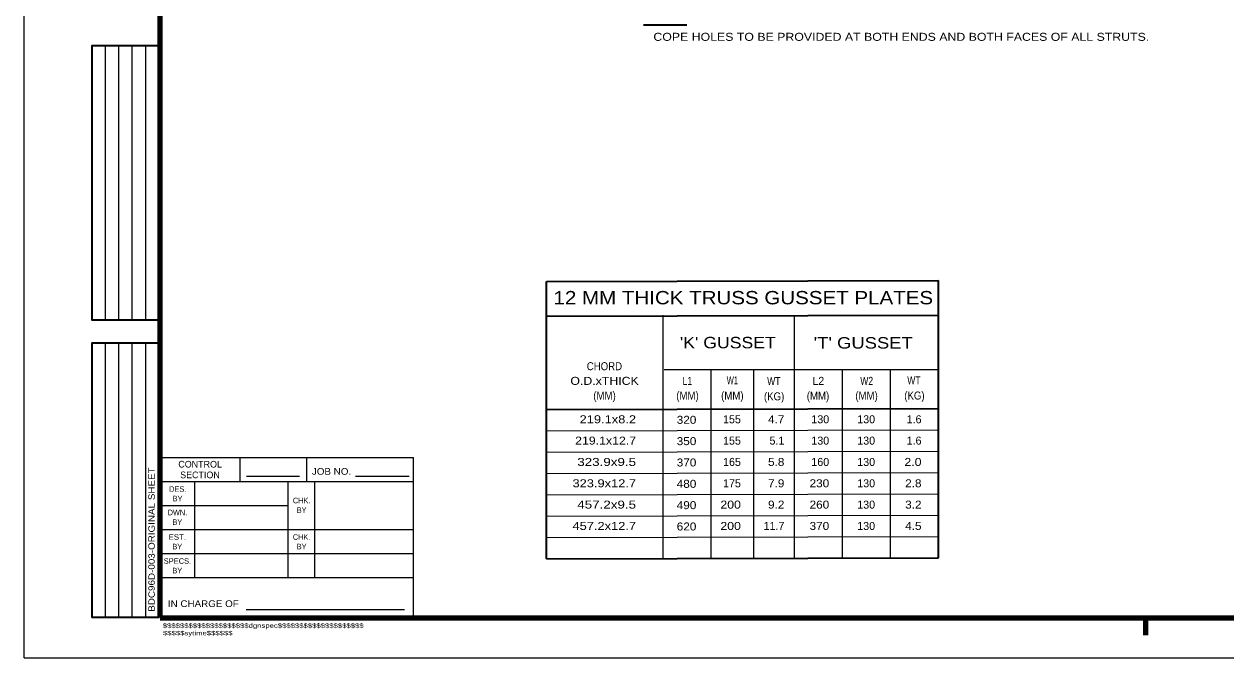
# Model space of a CAD drawing. Extents: x 312601.858 to 312602.699, y 144420.109 to 144420.704.
# Drawn here: x 312601.8578 to 312602.3083, y 144420.1095 to 144420.3472 of the extents above; entities that cross this region are included whole.
import ezdxf
from ezdxf.enums import TextEntityAlignment as Align

# ---------------------------------------------------------------- set-up
doc = ezdxf.new("R2010")
doc.units = 0
doc.header["$LTSCALE"] = 0.0012
for name, color, linetype, lineweight in [('1', 7, 'Continuous', 13), ('2', 7, 'Continuous', 13), ('39', 7, 'Continuous', 13), ('60', 7, 'Continuous', 25)]:
    doc.layers.add(name, color=color, linetype=linetype, lineweight=lineweight)

msp = doc.modelspace()

# ---------------------------------------------------------------- linework, layer by layer
at = {"layer": '1', "lineweight": 35}
for p, q in [((312602.0536, 144420.2507), (312602.2006, 144420.251)), ((312602.0536, 144420.1467), (312602.0536, 144420.2507)), ((312602.2006, 144420.147), (312602.2006, 144420.251)), ((312602.0536, 144420.2377), (312602.2006, 144420.238)), ((312602.0536, 144420.2027), (312602.2006, 144420.203)), ((312602.0536, 144420.1467), (312602.2006, 144420.147))]:
    msp.add_line(p, q, dxfattribs=at)
at = {"layer": '1', "lineweight": 25}
for p, q in [((312602.0974, 144420.147), (312602.0974, 144420.238)), ((312602.1466, 144420.147), (312602.1466, 144420.238)), ((312602.0977, 144420.2177), (312602.2006, 144420.2177))]:
    msp.add_line(p, q, dxfattribs=at)
at = {"layer": '1'}
for p, q in [((312602.1154, 144420.147), (312602.1154, 144420.2177)), ((312602.1314, 144420.147), (312602.1314, 144420.2177)), ((312602.1646, 144420.147), (312602.1646, 144420.2177)), ((312602.1826, 144420.147), (312602.1826, 144420.2177)), ((312602.0536, 144420.1947), (312602.2006, 144420.195)), ((312602.0536, 144420.1867), (312602.2006, 144420.187)), ((312602.0536, 144420.1787), (312602.2006, 144420.179)), ((312602.0536, 144420.1707), (312602.2006, 144420.171)), ((312602.0536, 144420.1627), (312602.2006, 144420.163)), ((312602.0536, 144420.1547), (312602.2006, 144420.155))]:
    msp.add_line(p, q, dxfattribs=at)
at = {"layer": '1', "lineweight": 158}
msp.add_line((312602.2783, 144420.1181), (312602.2783, 144420.1245), dxfattribs=at)
at = {"layer": '2', "lineweight": 35}
msp.add_line((312602.09, 144420.3469), (312602.1062, 144420.3469), dxfattribs=at)
at = {"layer": '39', "lineweight": 25}
for p, q in [((312601.8578, 144420.1095), (312601.8578, 144420.7035)), ((312601.9088, 144420.1847), (312602.0038, 144420.1847)), ((312602.0038, 144420.1247), (312602.0038, 144420.1847)), ((312601.8578, 144420.1095), (312602.6988, 144420.1095))]:
    msp.add_line(p, q, dxfattribs=at)
at = {"layer": '39'}
for p, q in [((312601.9088, 144420.1247), (312601.9088, 144420.1847)), ((312601.9388, 144420.1757), (312601.9388, 144420.1847)), ((312601.9638, 144420.1757), (312601.9638, 144420.1847)), ((312601.9088, 144420.1757), (312602.0038, 144420.1757)), ((312601.9218, 144420.1397), (312601.9218, 144420.1757)), ((312601.9412, 144420.1777), (312601.9611, 144420.1777)), ((312601.9568, 144420.1397), (312601.9568, 144420.1757)), ((312601.9668, 144420.1397), (312601.9668, 144420.1757)), ((312601.982, 144420.1777), (312602.0022, 144420.1777)), ((312601.9088, 144420.1667), (312601.9568, 144420.1667)), ((312601.9088, 144420.1577), (312602.0038, 144420.1577)), ((312601.9088, 144420.1487), (312602.0038, 144420.1487)), ((312601.9088, 144420.1397), (312602.0038, 144420.1397)), ((312601.9088, 144420.1247), (312602.0038, 144420.1247)), ((312601.941, 144420.1277), (312602.0004, 144420.1277))]:
    msp.add_line(p, q, dxfattribs=at)
at = {"layer": '39', "lineweight": 158}
for p, q in [((312601.9088, 144420.1245), (312602.6838, 144420.1245)), ((312602.2783, 144420.1181), (312602.2783, 144420.1245))]:
    msp.add_line(p, q, dxfattribs=at)
msp.add_lwpolyline([(312601.9088, 144420.1247), (312601.9088, 144420.6645), (312602.6838, 144420.6645)], dxfattribs=at)
at = {"layer": '60'}
for p, q in [((312601.8883, 144420.2361), (312601.8883, 144420.3391)), ((312601.8933, 144420.2361), (312601.8933, 144420.3391)), ((312601.8983, 144420.2361), (312601.8983, 144420.3391)), ((312601.9034, 144420.2361), (312601.9034, 144420.3391)), ((312601.8883, 144420.1247), (312601.8883, 144420.2277)), ((312601.8933, 144420.1247), (312601.8933, 144420.2277)), ((312601.8983, 144420.1247), (312601.8983, 144420.2277)), ((312601.9034, 144420.1247), (312601.9034, 144420.2277))]:
    msp.add_line(p, q, dxfattribs=at)
at = {"layer": '60', "lineweight": 35}
for points in [[(312601.9084, 144420.2361), (312601.8833, 144420.2361), (312601.8833, 144420.3391), (312601.9084, 144420.3391)], [(312601.9084, 144420.1247), (312601.8833, 144420.1247), (312601.8833, 144420.2277), (312601.9084, 144420.2277)]]:
    msp.add_lwpolyline(points, dxfattribs=at)

# ---------------------------------------------------------------- texts
at = {"layer": '1'}
for s, height, p in [('CONTROL', 0.0025, (312601.9238, 144420.1809)), ('SECTION', 0.0025, (312601.92375, 144420.1769)), ('DES.', 0.0021, (312601.9154, 144420.1718)), ('SPECS.', 0.0021, (312601.9153, 144420.1448))]:
    msp.add_text(s, height=height, dxfattribs=at).set_placement(p, align=Align.CENTER)
for s, height, width, p in [('JOB NO.', 0.0025, 1.1, (312601.97305, 144420.1782)), ('BY', 0.0021, 0.9, (312601.91535, 144420.1682)), ('CHK.', 0.0021, 0.95, (312601.96185, 144420.1675)), ('DWN.', 0.0021, 0.9, (312601.9153, 144420.163)), ('BY', 0.0021, 0.9, (312601.96185, 144420.1639)), ('BY', 0.0021, 0.9, (312601.91525, 144420.1594)), ('EST.', 0.0021, 1.05, (312601.91525, 144420.1538)), ('CHK.', 0.0021, 0.95, (312601.96185, 144420.1538)), ('BY', 0.0021, 0.9, (312601.91525, 144420.1502)), ('BY', 0.0021, 0.9, (312601.96185, 144420.1502)), ('BY', 0.0021, 0.9, (312601.91525, 144420.1412)), ('IN CHARGE OF', 0.0025, 1.1, (312601.925, 144420.1286))]:
    msp.add_text(s, height=height, dxfattribs=dict(at, width=width)).set_placement(p, align=Align.CENTER)
at = {"layer": '2'}
for s, height, width, p in [('COPE HOLES TO BE PROVIDED AT BOTH ENDS AND BOTH FACES OF ALL STRUTS.', 0.003, 1.15, (312602.0937, 144420.3409)), ('$$$$$$$$$$$$$$$$$$$$dgnspec$$$$$$$$$$$$$$$$$$$$', 0.001664, 1.3, (312601.9098, 144420.1208)), ('$$$$$sytime$$$$$$', 0.001664, 1.3, (312601.9099, 144420.118))]:
    msp.add_text(s, height=height, dxfattribs=dict(at, width=width)).set_placement(p)
for s, height, width, p in [('12 MM THICK TRUSS GUSSET PLATES', 0.005, 1.15, (312602.1274, 144420.2421)), ("'K' GUSSET", 0.0043, 1.15, (312602.1216, 144420.2256)), ("'T' GUSSET", 0.0043, 1.2, (312602.17235, 144420.2255)), ('CHORD', 0.003, 0.9, (312602.07535, 144420.2174)), ('O.D.xTHICK', 0.003, 1.15, (312602.0754, 144420.2119)), ('L1', 0.003, 0.8, (312602.10645, 144420.2119)), ('W1', 0.003, 0.7, (312602.1233, 144420.2121)), ('WT', 0.003, 0.8, (312602.13885, 144420.2118)), ('W2', 0.003, 0.8, (312602.17365, 144420.2119)), ('WT', 0.003, 0.8, (312602.19135, 144420.2121)), ('(MM)', 0.003, 0.9, (312602.0754, 144420.2064)), ('(MM)', 0.003, 0.9, (312602.1065, 144420.2064)), ('(MM)', 0.003, 0.9, (312602.1233, 144420.2064)), ('(KG)', 0.003, 0.9, (312602.13895, 144420.2061)), ('(MM)', 0.003, 0.9, (312602.1554, 144420.2063)), ('(MM)', 0.003, 0.9, (312602.1736, 144420.2064)), ('(KG)', 0.003, 0.9, (312602.19155, 144420.2064))]:
    msp.add_text(s, height=height, dxfattribs=dict(at, width=width)).set_placement(p, align=Align.CENTER)
msp.add_text('L2', height=0.003, dxfattribs=at).set_placement((312602.1555, 144420.2119), align=Align.CENTER)
for s, width, p in [('219.1x8.2', 1.2, (312602.0872, 144420.1975)), ('320', 1.1, (312602.1098, 144420.1973)), ('4.7', 1.1, (312602.1428, 144420.1975)), ('219.1x12.7', 1.15, (312602.0872, 144420.1895)), ('350', 1.1, (312602.1098, 144420.1893)), ('323.9x9.5', 1.25, (312602.0872, 144420.1815)), ('370', 1.1, (312602.1098, 144420.1813)), ('5.8', 1.1, (312602.1428, 144420.1815)), ('2.0', 1.15, (312602.1942, 144420.1815)), ('323.9x12.7', 1.2, (312602.0872, 144420.1735)), ('480', 1.1, (312602.1098, 144420.1733)), ('7.9', 1.1, (312602.1428, 144420.1735)), ('230', 1.1, (312602.1596, 144420.1735)), ('2.8', 1.1, (312602.1942, 144420.1735)), ('457.2x9.5', 1.25, (312602.0872, 144420.1655)), ('490', 1.1, (312602.1098, 144420.1653)), ('200', 1.15, (312602.1265, 144420.1655)), ('9.2', 1.1, (312602.1428, 144420.1655)), ('260', 1.1, (312602.1596, 144420.1655)), ('3.2', 1.1, (312602.1942, 144420.1655)), ('457.2x12.7', 1.2, (312602.0872, 144420.1575)), ('620', 1.1, (312602.1098, 144420.1573)), ('200', 1.15, (312602.1265, 144420.1575)), ('370', 1.1, (312602.1596, 144420.1575)), ('4.5', 1.1, (312602.1942, 144420.1575))]:
    msp.add_text(s, height=0.003, dxfattribs=dict(at, width=width)).set_placement(p, align=Align.RIGHT)
for s, p in [('155', (312602.1265, 144420.1975)), ('130', (312602.1596, 144420.1975)), ('130', (312602.1768, 144420.1975)), ('1.6', (312602.1942, 144420.1975)), ('155', (312602.1265, 144420.1895)), ('5.1', (312602.1428, 144420.1895)), ('130', (312602.1596, 144420.1895)), ('130', (312602.1768, 144420.1895)), ('1.6', (312602.1942, 144420.1895)), ('165', (312602.1265, 144420.1815)), ('160', (312602.1596, 144420.1815)), ('130', (312602.1768, 144420.1815)), ('175', (312602.1265, 144420.1735)), ('130', (312602.1768, 144420.1735)), ('130', (312602.1768, 144420.1655)), ('11.7', (312602.1428, 144420.1575)), ('130', (312602.1768, 144420.1575))]:
    msp.add_text(s, height=0.003, dxfattribs=at).set_placement(p, align=Align.RIGHT)
at = {"layer": '2', "width": 1.15}
msp.add_text('BDC96D-003-ORIGINAL SHEET', height=0.0024, rotation=90, dxfattribs=at).set_placement((312601.9068, 144420.1539), align=Align.CENTER)

doc.saveas('drawing.dxf')
